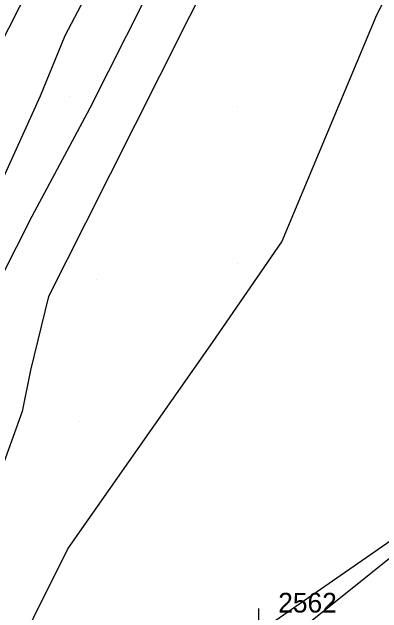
# Model space of a CAD drawing. Extents: x 2062781 to 2066835, y 358981 to 366501.
# Drawn here: x 2064126.5 to 2064173.5, y 361471.1 to 361547.4 of the extents above; entities that cross this region are included whole.
import ezdxf

# ---------------------------------------------------------------- set-up
doc = ezdxf.new("R2010")
doc.units = 0
for name, color, linetype in [('Exist DTM Breakline', 7, 'Continuous'), ('Exist DTM Ridgeline', 7, 'Continuous'), ('Exist DTM Ridgeline Cogo Number', 7, 'Continuous'), ('Exist DTM Ridgeline Cogo Point CELL', 7, 'Continuous'), ('Exist Roads EOP', 7, 'Continuous'), ('PH Exist DTM Breakline', 7, 'Continuous'), ('PH Exist DTM Point', 7, 'Continuous')]:
    doc.layers.add(name, color=color, linetype=linetype)

msp = doc.modelspace()

# ---------------------------------------------------------------- linework, layer by layer
at = {"layer": 'Exist DTM Breakline'}
msp.add_lwpolyline([(2064179.522, 361482.066), (2064149.285, 361457.883)], dxfattribs=at)
at = {"layer": 'Exist DTM Ridgeline'}
msp.add_lwpolyline([(2064157.807, 361468.649), (2064179.351, 361483.587), (2064201.333, 361505.698)], dxfattribs=at)
at = {"layer": 'Exist DTM Ridgeline Cogo Point CELL'}
msp.add_lwpolyline([(2064157.807, 361471.649), (2064157.807, 361465.649), (2064157.807, 361468.649), (2064160.807, 361468.649), (2064154.807, 361468.649)], dxfattribs=at)
msp.add_lwpolyline([(2064157.807, 361471.649), (2064157.807, 361465.649), (2064157.807, 361468.649), (2064160.807, 361468.649), (2064154.807, 361468.649)], dxfattribs=at)
msp.add_lwpolyline([(2064157.807, 361471.649), (2064157.807, 361465.649), (2064157.807, 361468.649), (2064160.807, 361468.649), (2064154.807, 361468.649)], dxfattribs=at)
at = {"layer": 'Exist Roads EOP'}
msp.add_lwpolyline([(2063968.74, 361236.858), (2063988.59, 361275.837), (2064007.944, 361313.553), (2064029.338, 361355.45), (2064050.744, 361397.355), (2064071.707, 361438.157), (2064092.469, 361479.256), (2064113.842, 361521.244), (2064134.238, 361561.364), (2064154.674, 361602.171), (2064176.641, 361645.096), (2064197.635, 361686.254), (2064219.165, 361728.913), (2064239.98, 361769.728), (2064260.768, 361810.546), (2064276.589, 361841.965)], dxfattribs=at)
at = {"layer": 'PH Exist DTM Breakline'}
for points in [[(2064190.717, 361645.188), (2064179.84, 361620.484), (2064168.688, 361597.509), (2064162.247, 361586.646), (2064154.244, 361570.703), (2064145.642, 361553.564), (2064136.409, 361535.169), (2064129.04, 361521.397), (2064123.089, 361509.693), (2064116.949, 361498.007), (2064108.836, 361481.844), (2064099.998, 361462.136)], [(2064078.941, 361375.618), (2064096.39, 361407.467), (2064116.272, 361444.439), (2064133.606, 361479.232), (2064151.973, 361505.442), (2064160.76, 361518.208), (2064172.834, 361547.027), (2064190.561, 361582.129), (2064206.147, 361613.547), (2064218.65, 361638.457)], [(2064106.091, 361492.289), (2064107.074, 361494.958), (2064109.329, 361498.79), (2064112.296, 361503.588), (2064116.283, 361509.502), (2064119.123, 361517.24), (2064121.938, 361521.834), (2064125.067, 361525.532), (2064130.12, 361536.715), (2064133.255, 361544.38), (2064136.917, 361551.323), (2064141.95, 361562.16), (2064146.471, 361572.133), (2064151.107, 361582.889), (2064154.904, 361591.52), (2064158.117, 361596.907), (2064163.177, 361605.617), (2064166.022, 361610.425)], [(2064169.73, 361588.421), (2064160.776, 361570.227), (2064152.848, 361554.43), (2064145.223, 361539.239), (2064135.861, 361520.588), (2064131.171, 361511.243), (2064128.874, 361501.931), (2064127.814, 361496.654), (2064124.292, 361486.999), (2064113.821, 361470.956), (2064105.667, 361458.423), (2064101.064, 361449.809), (2064096.582, 361440.88), (2064094.206, 361431.846), (2064089.171, 361420.333), (2064084.102, 361412.172), (2064081.203, 361402.724), (2064079.126, 361400.31), (2064075.785, 361398.219), (2064073.627, 361396.707), (2064071.474, 361392.468), (2064069.936, 361385.095), (2064071.015, 361378.419), (2064070.798, 361376.416)]]:
    msp.add_lwpolyline(points, dxfattribs=at)
at = {"layer": 'PH Exist DTM Point'}
for p, q in [((2064133.772, 361536.614), (2064133.772, 361536.614)), ((2064155.132, 361535.384), (2064155.132, 361535.384)), ((2064155.111, 361515.395), (2064155.111, 361515.395)), ((2064137.188, 361513.364), (2064137.188, 361513.364)), ((2064135.132, 361495.384), (2064135.132, 361495.384))]:
    msp.add_line(p, q, dxfattribs=at)

# ---------------------------------------------------------------- texts
at = {"layer": 'Exist DTM Ridgeline Cogo Number'}
msp.add_text('2562', height=2.5, dxfattribs=at).set_placement((2064160.307, 361471.149))
msp.add_text('2562', height=2.5, dxfattribs=at).set_placement((2064160.307, 361471.149))
msp.add_text('2562', height=2.5, dxfattribs=at).set_placement((2064160.307, 361471.149))

doc.saveas('drawing.dxf')
